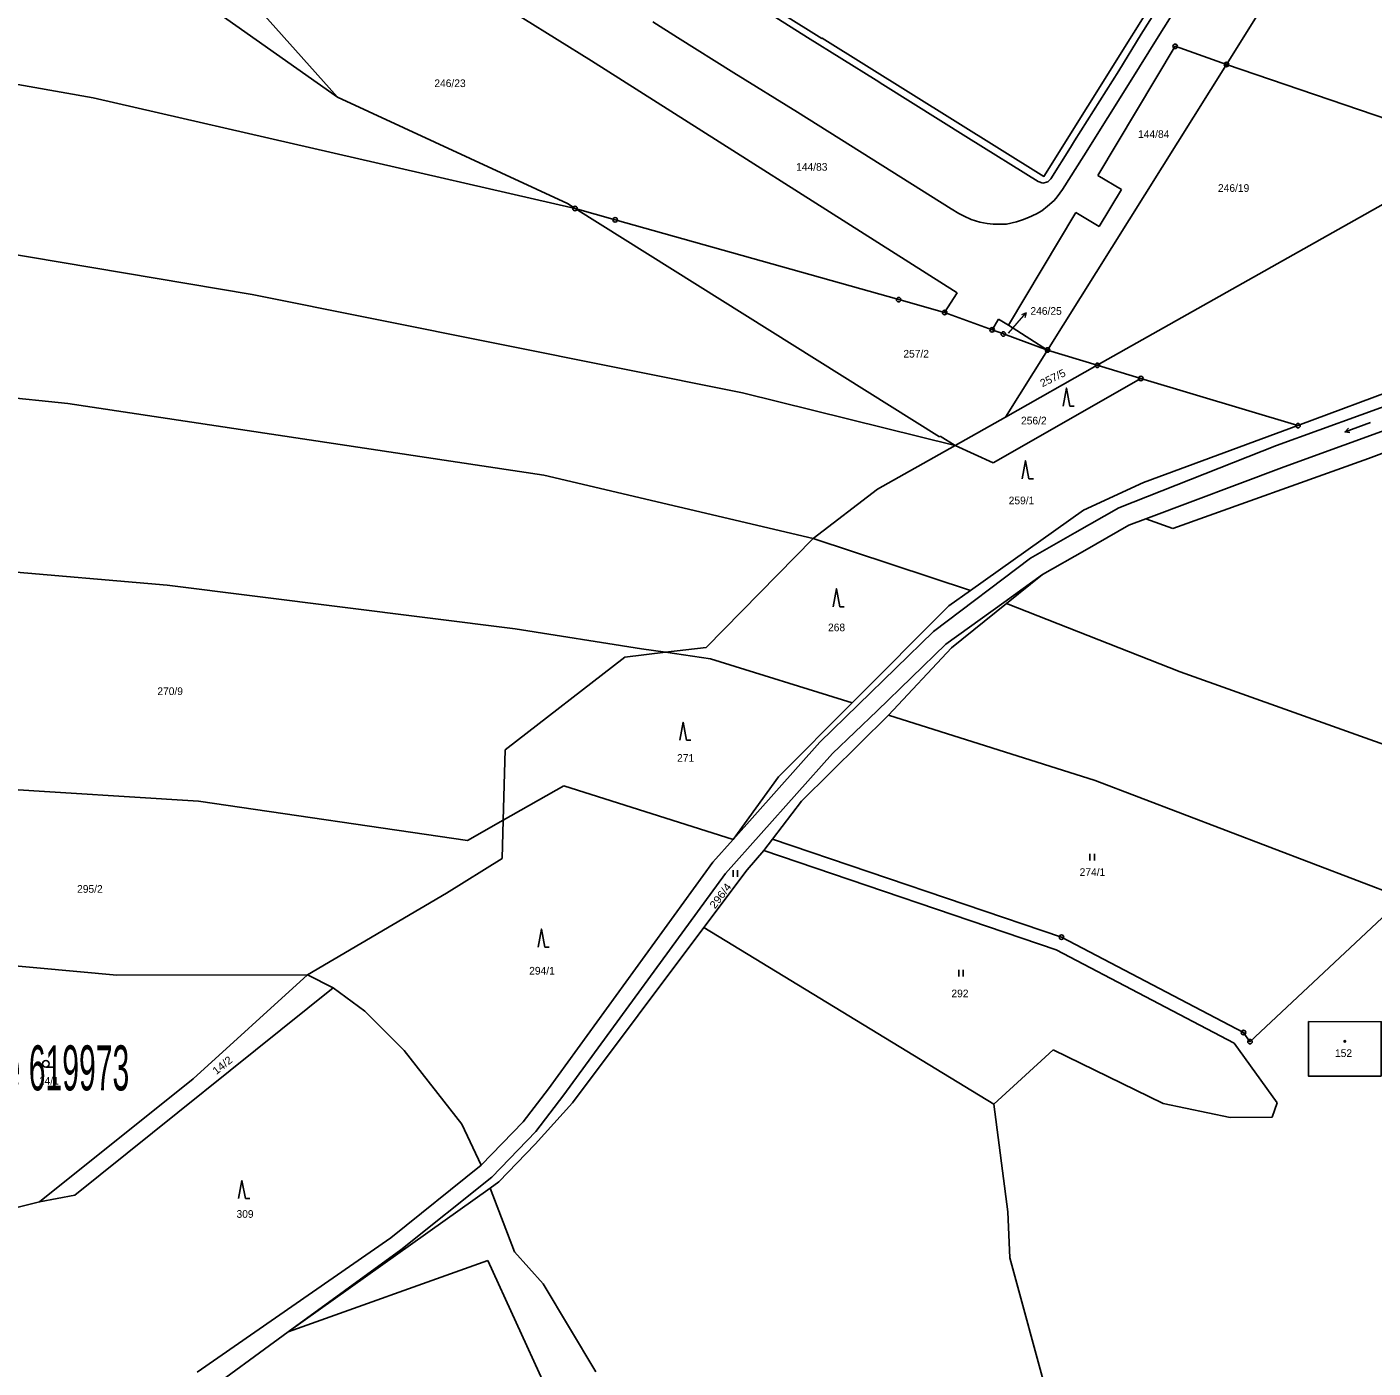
# Model space of a CAD drawing. Extents: x -645290 to -643454, y -1064771 to -1062356.
# Drawn here: x -644423.3 to -644124.4, y -1063667.6 to -1063369.7 of the extents above; entities that cross this region are included whole.
import ezdxf
from ezdxf.enums import TextEntityAlignment as Align

# ---------------------------------------------------------------- set-up
doc = ezdxf.new("R2010")
doc.units = 0
doc.header["$LTSCALE"] = 0.68
for name, color, linetype, lineweight in [('1', 7, 'Continuous', 25), ('3', 7, 'Continuous', 25), ('5', 7, 'Continuous', 25), ('7', 7, 'Continuous', 13), ('8', 7, 'Continuous', 25)]:
    doc.layers.add(name, color=color, linetype=linetype, lineweight=lineweight)
doc.layers.add('2', color=7, linetype='Continuous')

msp = doc.modelspace()

# ---------------------------------------------------------------- linework, layer by layer
at = {"layer": '1'}
for p, q in [((-644405.68, -1063310.31), (-644297.96, -1063377.21)), ((-644354.41, -1063385.34), (-644456.76, -1063312.9)), ((-644411.05, -1063321.67), (-644354.41, -1063385.34)), ((-644157, -1063378.05), (-644128.32, -1063332.26)), ((-644250, -1063372.02), (-644265.68, -1063362.14)), ((-644170.57, -1063362.75), (-644175.9, -1063371.34)), ((-644167.65, -1063364.69), (-644172.52, -1063372.53)), ((-644278.9, -1063372.05), (-644284.36, -1063368.55)), ((-644266.35, -1063379.87), (-644278.9, -1063372.05)), ((-644234.78, -1063381.56), (-644250, -1063372.02)), ((-644175.9, -1063371.34), (-644180.93, -1063379.44)), ((-644172.52, -1063372.53), (-644177.98, -1063381.3)), ((-644185.52, -1063402.7), (-644168.39, -1063374.01)), ((-644157, -1063378.05), (-644168.39, -1063374.01)), ((-644452.09, -1063377.81), (-644408.67, -1063385.46)), ((-644297.96, -1063377.21), (-644216.81, -1063428.73)), ((-644196.72, -1063441.48), (-644157, -1063378.05)), ((-644157, -1063378.05), (-644100.19, -1063397.44)), ((-644252.28, -1063388.64), (-644266.35, -1063379.87)), ((-644233.32, -1063382.49), (-644234.78, -1063381.56)), ((-644180.93, -1063379.44), (-644190.73, -1063395.04)), ((-644177.98, -1063381.3), (-644188.7, -1063398.35)), ((-644214.25, -1063394.43), (-644233.32, -1063382.49)), ((-644408.67, -1063385.46), (-644301.65, -1063410.03)), ((-644303.34, -1063408.96), (-644354.41, -1063385.34)), ((-644235.92, -1063398.9), (-644252.28, -1063388.64)), ((-644198.77, -1063404.07), (-644214.25, -1063394.43)), ((-644191.62, -1063396.48), (-644195.96, -1063403.43)), ((-644190.73, -1063395.04), (-644191.62, -1063396.48)), ((-644218.11, -1063410.09), (-644235.92, -1063398.9)), ((-644188.7, -1063398.35), (-644193.39, -1063405.85)), ((-644180.32, -1063405.81), (-644185.52, -1063402.7)), ((-644197.77, -1063404.39), (-644198.77, -1063404.07)), ((-644196.69, -1063404.09), (-644197.77, -1063404.39)), ((-644195.96, -1063403.43), (-644196.69, -1063404.09)), ((-644193.39, -1063405.85), (-644194.55, -1063407.45)), ((-644185.25, -1063414.05), (-644180.32, -1063405.81)), ((-644301.65, -1063410.03), (-644303.34, -1063408.96)), ((-644195.22, -1063408.25), (-644196.77, -1063409.55)), ((-644194.55, -1063407.45), (-644195.22, -1063408.25)), ((-644119.82, -1063407.74), (-644185.68, -1063444.87)), ((-644220.7, -1063460.76), (-644301.65, -1063410.03)), ((-644301.65, -1063410.03), (-644292.74, -1063412.54)), ((-644216.44, -1063411.11), (-644218.11, -1063410.09)), ((-644215.27, -1063411.77), (-644216.44, -1063411.11)), ((-644213.71, -1063412.45), (-644215.27, -1063411.77)), ((-644205.39, -1063435.98), (-644190.44, -1063410.95)), ((-644200.95, -1063412.05), (-644202.26, -1063412.57)), ((-644199.2, -1063411.21), (-644200.95, -1063412.05)), ((-644198.01, -1063410.52), (-644199.2, -1063411.21)), ((-644196.77, -1063409.55), (-644198.01, -1063410.52)), ((-644190.44, -1063410.95), (-644185.25, -1063414.05)), ((-644292.74, -1063412.54), (-644229.78, -1063430.27)), ((-644211.78, -1063413.06), (-644213.71, -1063412.45)), ((-644210.11, -1063413.4), (-644211.78, -1063413.06)), ((-644208.83, -1063413.52), (-644210.11, -1063413.4)), ((-644207.13, -1063413.54), (-644208.83, -1063413.52)), ((-644205.8, -1063413.5), (-644207.13, -1063413.54)), ((-644203.62, -1063412.99), (-644205.8, -1063413.5)), ((-644202.26, -1063412.57), (-644203.62, -1063412.99)), ((-644373.36, -1063429.14), (-644451.47, -1063416.02)), ((-644141.12, -1063458.26), (-644040.14, -1063420.35)), ((-644264.43, -1063450.96), (-644373.36, -1063429.14)), ((-644216.81, -1063428.73), (-644219.58, -1063433.14)), ((-644229.78, -1063430.27), (-644219.58, -1063433.14)), ((-644064.06, -1063433), (-644145.92, -1063462.71)), ((-644219.58, -1063433.14), (-644209.03, -1063436.99)), ((-644207.59, -1063434.58), (-644209.03, -1063436.99)), ((-644207.59, -1063434.58), (-644205.39, -1063435.98)), ((-644205.39, -1063435.98), (-644196.72, -1063441.48)), ((-644209.03, -1063436.99), (-644206.53, -1063437.9)), ((-644196.72, -1063441.48), (-644206.53, -1063437.9)), ((-644144.15, -1063467.38), (-644062.18, -1063437.63)), ((-644206.03, -1063456.35), (-644196.72, -1063441.48)), ((-644196.72, -1063441.48), (-644185.68, -1063444.87)), ((-644414.26, -1063453.35), (-644500.64, -1063444.4)), ((-644185.68, -1063444.87), (-644206.03, -1063456.35)), ((-644185.68, -1063444.87), (-644176.01, -1063447.79)), ((-644176.01, -1063447.79), (-644208.82, -1063466.56)), ((-644176.01, -1063447.79), (-644141.12, -1063458.26)), ((-644264.43, -1063450.96), (-644217.24, -1063462.67)), ((-644308.54, -1063469.25), (-644414.26, -1063453.35)), ((-644206.03, -1063456.35), (-644217.24, -1063462.67)), ((-644141.12, -1063458.26), (-644175.45, -1063470.92)), ((-644234.49, -1063472.39), (-644217.24, -1063462.67)), ((-644220.58, -1063460.58), (-644220.7, -1063460.76)), ((-644217.24, -1063462.67), (-644220.58, -1063460.58)), ((-644208.82, -1063466.56), (-644217.24, -1063462.67)), ((-644145.92, -1063462.71), (-644180.87, -1063476.51)), ((-644168.9, -1063481.09), (-644125.49, -1063465.59)), ((-644144.15, -1063467.38), (-644174.88, -1063478.99)), ((-644248.76, -1063483.35), (-644308.54, -1063469.25)), ((-644175.45, -1063470.92), (-644188.72, -1063477.03)), ((-644248.76, -1063483.35), (-644234.49, -1063472.39)), ((-644213.82, -1063494.9), (-644188.72, -1063477.03)), ((-644180.87, -1063476.51), (-644190.65, -1063482.09)), ((-644178.64, -1063480.41), (-644188.44, -1063486.01)), ((-644174.88, -1063478.99), (-644178.64, -1063480.41)), ((-644174.88, -1063478.99), (-644168.9, -1063481.09)), ((-644272.5, -1063507.55), (-644248.76, -1063483.35)), ((-644213.82, -1063494.9), (-644248.76, -1063483.35)), ((-644190.65, -1063482.09), (-644200.52, -1063487.7)), ((-644487.41, -1063485.57), (-644392.24, -1063493.71)), ((-644188.44, -1063486.01), (-644197.88, -1063491.34)), ((-644200.52, -1063487.7), (-644222.07, -1063503.96)), ((-644197.88, -1063491.34), (-644206.46, -1063497.55)), ((-644205.87, -1063497.78), (-644197.88, -1063491.34)), ((-644392.24, -1063493.71), (-644314.95, -1063503.39)), ((-644218.62, -1063498.31), (-644213.82, -1063494.9)), ((-644240.12, -1063519.85), (-644218.62, -1063498.31)), ((-644206.46, -1063497.55), (-644219.3, -1063506.84)), ((-644218.08, -1063507.64), (-644205.87, -1063497.78)), ((-644205.87, -1063497.78), (-644167.24, -1063512.95)), ((-644314.95, -1063503.39), (-644286.89, -1063507.85)), ((-644222.07, -1063503.96), (-644238.78, -1063520.27)), ((-644281.53, -1063508.61), (-644286.89, -1063507.85)), ((-644272.5, -1063507.55), (-644281.53, -1063508.61)), ((-644219.3, -1063506.84), (-644234.59, -1063521.58)), ((-644232.05, -1063522.56), (-644218.08, -1063507.64)), ((-644290.56, -1063509.68), (-644317.16, -1063530.31)), ((-644281.53, -1063508.61), (-644290.56, -1063509.68)), ((-644271.53, -1063510.04), (-644281.53, -1063508.61)), ((-644240.12, -1063519.85), (-644271.53, -1063510.04)), ((-644080.22, -1063544.05), (-644167.24, -1063512.95)), ((-644256.5, -1063536.27), (-644240.12, -1063519.85)), ((-644232.05, -1063522.56), (-644251.37, -1063541.71)), ((-644238.78, -1063520.27), (-644247.3, -1063528.58)), ((-644234.59, -1063521.58), (-644244.47, -1063531.11)), ((-644186.18, -1063537.07), (-644232.05, -1063522.56)), ((-644247.3, -1063528.58), (-644266.56, -1063550.18)), ((-644317.16, -1063530.31), (-644317.59, -1063545.92)), ((-644244.47, -1063531.11), (-644268.2, -1063557.73)), ((-644472.86, -1063536.21), (-644385.25, -1063541.67)), ((-644266.56, -1063550.18), (-644256.5, -1063536.27)), ((-644118.31, -1063562.97), (-644186.18, -1063537.07)), ((-644317.59, -1063545.92), (-644304.11, -1063538.3)), ((-644304.11, -1063538.3), (-644266.56, -1063550.18)), ((-644385.25, -1063541.67), (-644325.52, -1063550.41)), ((-644257.82, -1063550.11), (-644251.37, -1063541.71)), ((-644325.52, -1063550.41), (-644317.59, -1063545.92)), ((-644317.59, -1063545.92), (-644317.82, -1063554.43)), ((-644266.56, -1063550.18), (-644271.04, -1063555.2)), ((-644259.75, -1063552.62), (-644263.44, -1063556.95)), ((-644259.75, -1063552.62), (-644257.82, -1063550.11)), ((-644257.82, -1063550.11), (-644193.63, -1063571.9)), ((-644317.82, -1063554.43), (-644330.17, -1063562.12)), ((-644271.04, -1063555.2), (-644307.53, -1063605.55)), ((-644268.2, -1063557.73), (-644304.12, -1063606.89)), ((-644263.44, -1063556.95), (-644273.04, -1063569.75)), ((-644330.17, -1063562.12), (-644361.08, -1063580.23)), ((-644151.77, -1063595.11), (-644117.73, -1063563.22)), ((-644208.62, -1063608.96), (-644273.04, -1063569.75)), ((-644193.63, -1063571.9), (-644153.23, -1063593.07)), ((-644403.42, -1063580.33), (-644454.17, -1063575.65)), ((-644361.08, -1063580.23), (-644403.42, -1063580.33)), ((-644361.08, -1063580.23), (-644386.47, -1063603.34)), ((-644355.38, -1063583.14), (-644361.08, -1063580.23)), ((-644412.74, -1063629.18), (-644355.38, -1063583.14)), ((-644348.28, -1063588.35), (-644355.38, -1063583.14)), ((-644339.58, -1063597.04), (-644348.28, -1063588.35)), ((-644153.23, -1063593.07), (-644151.77, -1063595.11)), ((-644326.77, -1063613.41), (-644339.58, -1063597.04)), ((-644195.44, -1063596.88), (-644208.62, -1063608.96)), ((-644171.04, -1063608.82), (-644195.44, -1063596.88)), ((-644155.25, -1063595.4), (-644145.71, -1063608.71)), ((-644386.47, -1063603.34), (-644420.53, -1063630.64)), ((-644307.53, -1063605.55), (-644313.14, -1063612.91)), ((-644304.12, -1063606.89), (-644310.31, -1063615.02)), ((-644208.62, -1063608.96), (-644205.51, -1063632.91)), ((-644156.19, -1063611.94), (-644171.04, -1063608.82)), ((-644145.71, -1063608.71), (-644146.82, -1063611.88)), ((-644146.82, -1063611.88), (-644156.19, -1063611.94)), ((-644322.5, -1063622.5), (-644326.77, -1063613.41)), ((-644313.14, -1063612.91), (-644322.5, -1063622.5)), ((-644310.31, -1063615.02), (-644320.14, -1063625.22)), ((-644318.57, -1063626.27), (-644310.53, -1063617.89)), ((-644322.5, -1063622.5), (-644342.53, -1063638.64)), ((-644320.14, -1063625.22), (-644340.34, -1063641.37)), ((-644320.51, -1063627.65), (-644318.57, -1063626.27)), ((-644420.53, -1063630.64), (-644412.74, -1063629.18)), ((-644365.33, -1063659.58), (-644320.51, -1063627.65)), ((-644315.08, -1063641.76), (-644320.51, -1063627.65)), ((-644420.53, -1063630.64), (-644437.84, -1063635.07)), ((-644205.51, -1063632.91), (-644205.13, -1063643.13)), ((-644342.53, -1063638.64), (-644385.58, -1063668.54)), ((-644340.34, -1063641.37), (-644365.33, -1063659.58)), ((-644308.72, -1063648.86), (-644315.08, -1063641.76)), ((-644321, -1063643.72), (-644365.33, -1063659.58)), ((-644308.43, -1063671.28), (-644321, -1063643.72)), ((-644205.13, -1063643.13), (-644193.31, -1063686.18)), ((-644297.05, -1063668.47), (-644308.72, -1063648.86)), ((-644365.33, -1063659.58), (-644395.9, -1063681.86))]:
    msp.add_line(p, q, dxfattribs=at)
for points in [[(-644162.87, -1063200.63), (-644154.86, -1063187.84), (-644138.14, -1063198.3), (-644138.19, -1063198.38), (-644088.93, -1063229.19), (-644197.53, -1063402.92), (-644246.76, -1063372.17), (-644246.82, -1063372.26), (-644263.58, -1063361.75), (-644255.56, -1063348.85)], [(-644080.48, -1063473.96), (-644122.49, -1063464.47), (-644125.49, -1063465.59)], [(-644259.75, -1063552.62), (-644194.82, -1063574.67), (-644155.25, -1063595.4)], [(-644273.04, -1063569.75), (-644302.23, -1063608.67), (-644310.53, -1063617.89)]]:
    msp.add_lwpolyline(points, dxfattribs=at)
msp.add_lwpolyline([(-644122.64, -1063602.77), (-644138.8, -1063602.73), (-644138.77, -1063590.65), (-644122.61, -1063590.66)], close=True, dxfattribs=at)
at = {"layer": '3'}
for p, q in [((-644191.79, -1063453.91), (-644190.794, -1063453.91)), ((-644130.658, -1063459.654), (-644129.911, -1063458.848)), ((-644200.87, -1063470.07), (-644199.874, -1063470.07)), ((-644242.86, -1063498.49), (-644241.864, -1063498.49)), ((-644276.9, -1063528.16), (-644275.904, -1063528.16)), ((-644187.331, -1063554.86), (-644187.331, -1063553.36)), ((-644186.33, -1063554.86), (-644186.33, -1063553.36)), ((-644266.541, -1063558.52), (-644266.541, -1063557.02)), ((-644265.54, -1063558.52), (-644265.54, -1063557.02)), ((-644308.36, -1063574.09), (-644307.364, -1063574.09)), ((-644216.441, -1063580.64), (-644216.441, -1063579.14)), ((-644215.44, -1063580.64), (-644215.44, -1063579.14)), ((-644419.143, -1063600.77), (-644417.393, -1063600.77)), ((-644374.85, -1063629.97), (-644373.854, -1063629.97))]:
    msp.add_line(p, q, dxfattribs=at)
for points in [[(-644191.79, -1063453.91), (-644192.54, -1063449.91), (-644193.29, -1063453.91)], [(-644125.02, -1063457.602), (-644130.658, -1063459.654), (-644129.568, -1063459.791)], [(-644200.87, -1063470.07), (-644201.62, -1063466.07), (-644202.37, -1063470.07)], [(-644242.86, -1063498.49), (-644243.61, -1063494.49), (-644244.36, -1063498.49)], [(-644276.9, -1063528.16), (-644277.65, -1063524.16), (-644278.4, -1063528.16)], [(-644308.36, -1063574.09), (-644309.11, -1063570.09), (-644309.86, -1063574.09)], [(-644374.85, -1063629.97), (-644375.6, -1063625.97), (-644376.35, -1063629.97)]]:
    msp.add_lwpolyline(points, dxfattribs=at)
msp.add_circle((-644419.1429, -1063600.0198), 0.75, dxfattribs=at)
at = {"layer": '5'}
msp.add_circle((-644130.7068, -1063595.0192), 0.175, dxfattribs=at)
at = {"layer": '7'}
msp.add_line((-644201.501, -1063433.235), (-644202.536, -1063433.662), dxfattribs=at)
msp.add_lwpolyline([(-644205.4, -1063437.74), (-644203.47, -1063435.5), (-644201.501, -1063433.235), (-644201.78, -1063434.319)], dxfattribs=at)
at = {"layer": '8'}
for centre, radius in [((-644168.39, -1063374.0099), 0.5), ((-644168.39, -1063374.0099), 0.0303), ((-644157, -1063378.0499), 0.5), ((-644157, -1063378.0499), 0.0303), ((-644301.65, -1063410.0299), 0.5), ((-644301.65, -1063410.0299), 0.0303), ((-644292.74, -1063412.5399), 0.5), ((-644292.74, -1063412.5399), 0.0303), ((-644229.78, -1063430.2699), 0.5), ((-644229.78, -1063430.2699), 0.0303), ((-644219.58, -1063433.1399), 0.5), ((-644219.58, -1063433.1399), 0.0303), ((-644209.03, -1063436.9899), 0.5), ((-644209.03, -1063436.9899), 0.0303), ((-644206.53, -1063437.8999), 0.5), ((-644206.53, -1063437.8999), 0.0303), ((-644196.72, -1063441.4799), 0.5), ((-644196.72, -1063441.4799), 0.0303), ((-644185.68, -1063444.8699), 0.5), ((-644185.68, -1063444.8699), 0.0303), ((-644176.01, -1063447.7899), 0.5), ((-644176.01, -1063447.7899), 0.0303), ((-644141.12, -1063458.2599), 0.5), ((-644141.12, -1063458.2599), 0.0303), ((-644193.63, -1063571.8999), 0.5), ((-644193.63, -1063571.8999), 0.0303), ((-644153.23, -1063593.0699), 0.5), ((-644153.23, -1063593.0699), 0.0303), ((-644151.77, -1063595.1099), 0.5), ((-644151.77, -1063595.1099), 0.0303)]:
    msp.add_circle(centre, radius, dxfattribs=at)

# ---------------------------------------------------------------- texts
at = {"layer": '2'}
for s, height, p in [('246/23', 1.7, (-644332.88, -1063383.064)), ('246/19', 1.7, (-644158.88, -1063406.334)), ('246/25', 1.7, (-644200.52, -1063433.645)), ('246/25', 0.2, (-644205.4, -1063437.79)), ('257/2', 1.7, (-644228.74, -1063443.145)), ('256/2', 1.7, (-644202.61, -1063457.995)), ('259/1', 1.7, (-644205.35, -1063475.735)), ('268', 1.7, (-644245.47, -1063503.935)), ('270/9', 1.7, (-644394.39, -1063518.104)), ('271', 1.7, (-644278.98, -1063532.935)), ('295/2', 1.7, (-644412.21, -1063562.025)), ('292', 1.7, (-644218.07, -1063585.235)), ('14/1', 1.7, (-644420.69, -1063604.635)), ('309', 1.7, (-644376.81, -1063634.225))]:
    msp.add_text(s, height=height, dxfattribs=at).set_placement(p)
for s, p in [('144/84', (-644173.15, -1063394.365)), ('144/83', (-644249.07, -1063401.645)), ('274/1', (-644186.75, -1063558.285)), ('294/1', (-644308.98, -1063580.195)), ('152', (-644130.999, -1063598.495))]:
    msp.add_text(s, height=1.7, dxfattribs=at).set_placement(p, align=Align.CENTER)
for s, rotation, width, p in [('257/5', 26, 1.05, (-644197.873, -1063449.751)), ('296/4', 53, 1.1, (-644270.56, -1063565.715)), ('14/2', 39, 1.1, (-644381.302, -1063602.54))]:
    msp.add_text(s, height=1.7, rotation=rotation, dxfattribs=dict(at, width=width)).set_placement(p)
at = {"layer": '7', "width": 0.5}
msp.add_text('Drozdice 619973', height=10, dxfattribs=at).set_placement((-644425.9, -1063605.923), align=Align.CENTER)

doc.saveas('drawing.dxf')
